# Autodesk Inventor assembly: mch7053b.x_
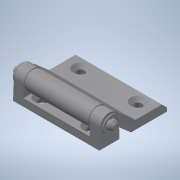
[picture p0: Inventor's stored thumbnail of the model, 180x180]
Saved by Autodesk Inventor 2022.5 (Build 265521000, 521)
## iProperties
Part Number: mch7053b.x_
Material: 一般
Document SubType Name: Assembly
Designer: ImaoCorp
Sending System: SOLIDWORKS 2017-2017317
MC: AMD64
MC_MODEL: Intel64 Family 6 Model 60 Stepping 3, GenuineIntel
OS: Windows_NT
FRU: Parasolid Version 29.0, build 201,  4-17-2017
FORMAT: text
GUISE: transmit
KEY: mch7053b
FILE: mch7053b.x_t
DATE: Fri Jul 26 11:41:43 2019
Author: ImaoCorp
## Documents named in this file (4)
- X:\14_SW2022-Inv2022\00_全2023-1023新製品(TCC)まで\m\mch7053b\MCH7053B.iam
- X:\14_SW2022-Inv2022\00_全2023-1023新製品(TCC)まで\m\mch7053b\mch7053b_01.ipt
- X:\14_SW2022-Inv2022\00_全2023-1023新製品(TCC)まで\m\mch7053b\mch7053b_02.ipt
- X:\14_SW2022-Inv2022\00_全2023-1023新製品(TCC)まで\m\mch7053b\mch7053b_03.ipt
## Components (3 placed, 3 different names)
1. mch7053b_01
2. mch7053b_02
3. mch7053b_03
